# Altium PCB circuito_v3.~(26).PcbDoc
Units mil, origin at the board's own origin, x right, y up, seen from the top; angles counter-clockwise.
Board outline 6000 x 4000 mil, 2 copper layers (Top Layer, Bottom Layer); 47 components, 32 nets, 112 pads, 55 vias.
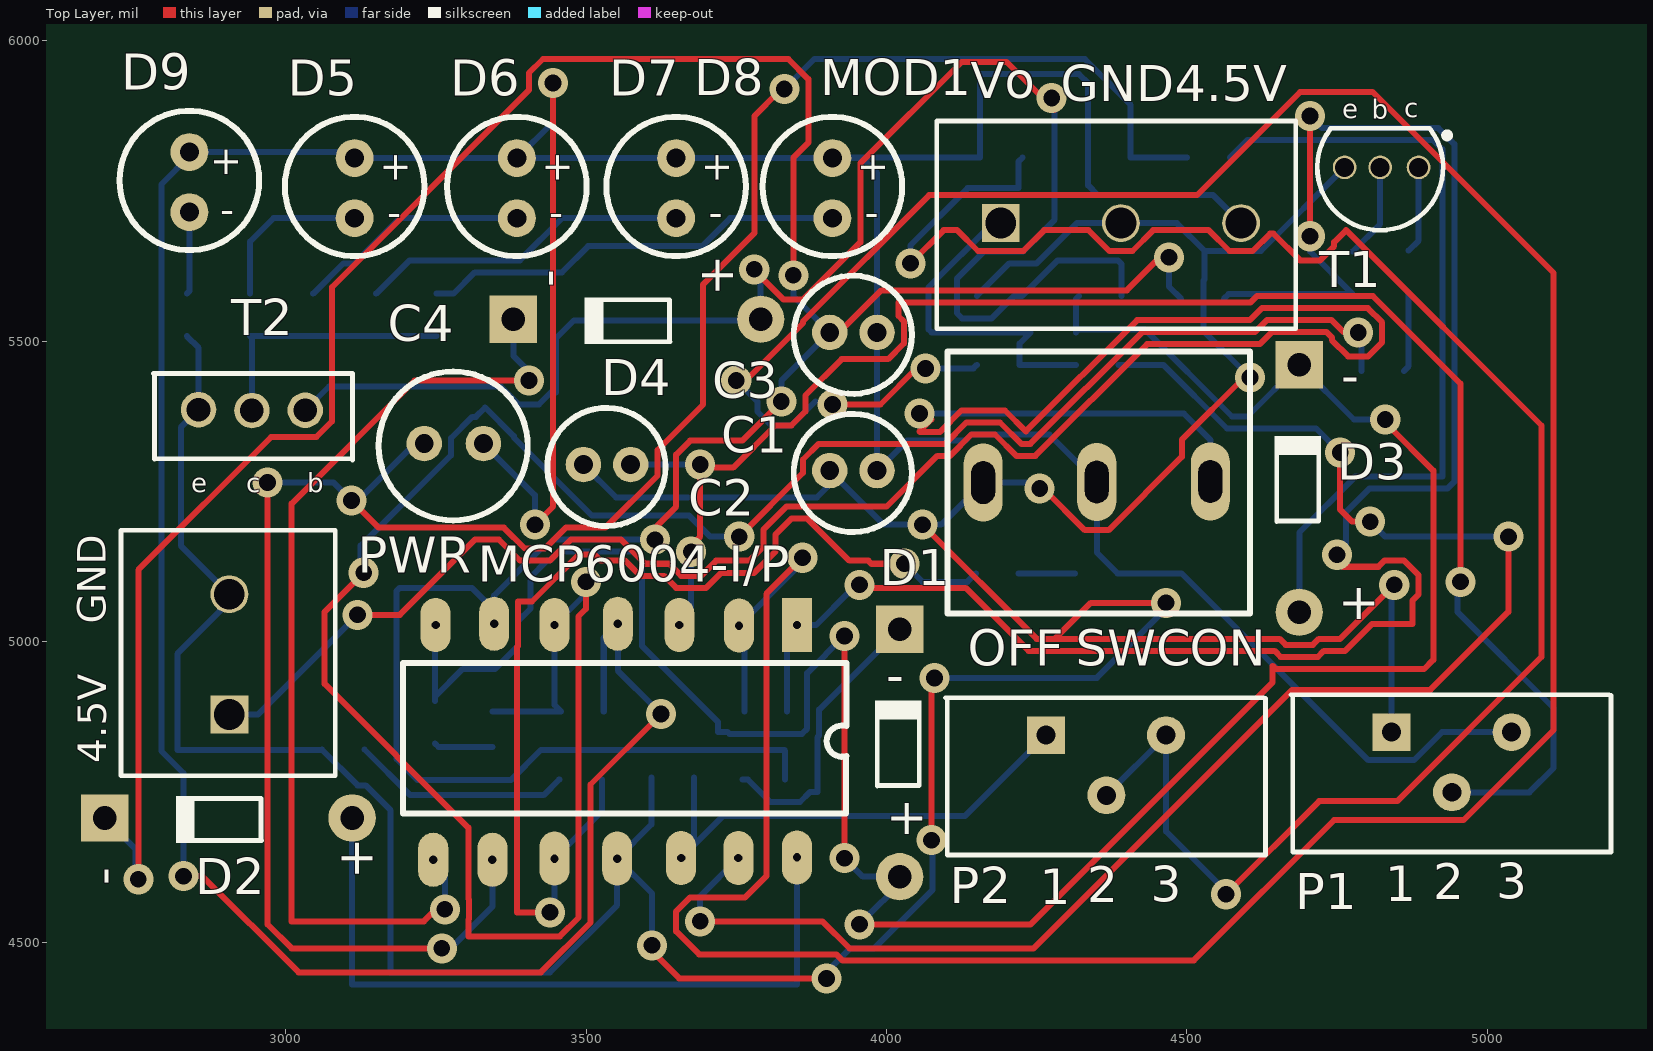
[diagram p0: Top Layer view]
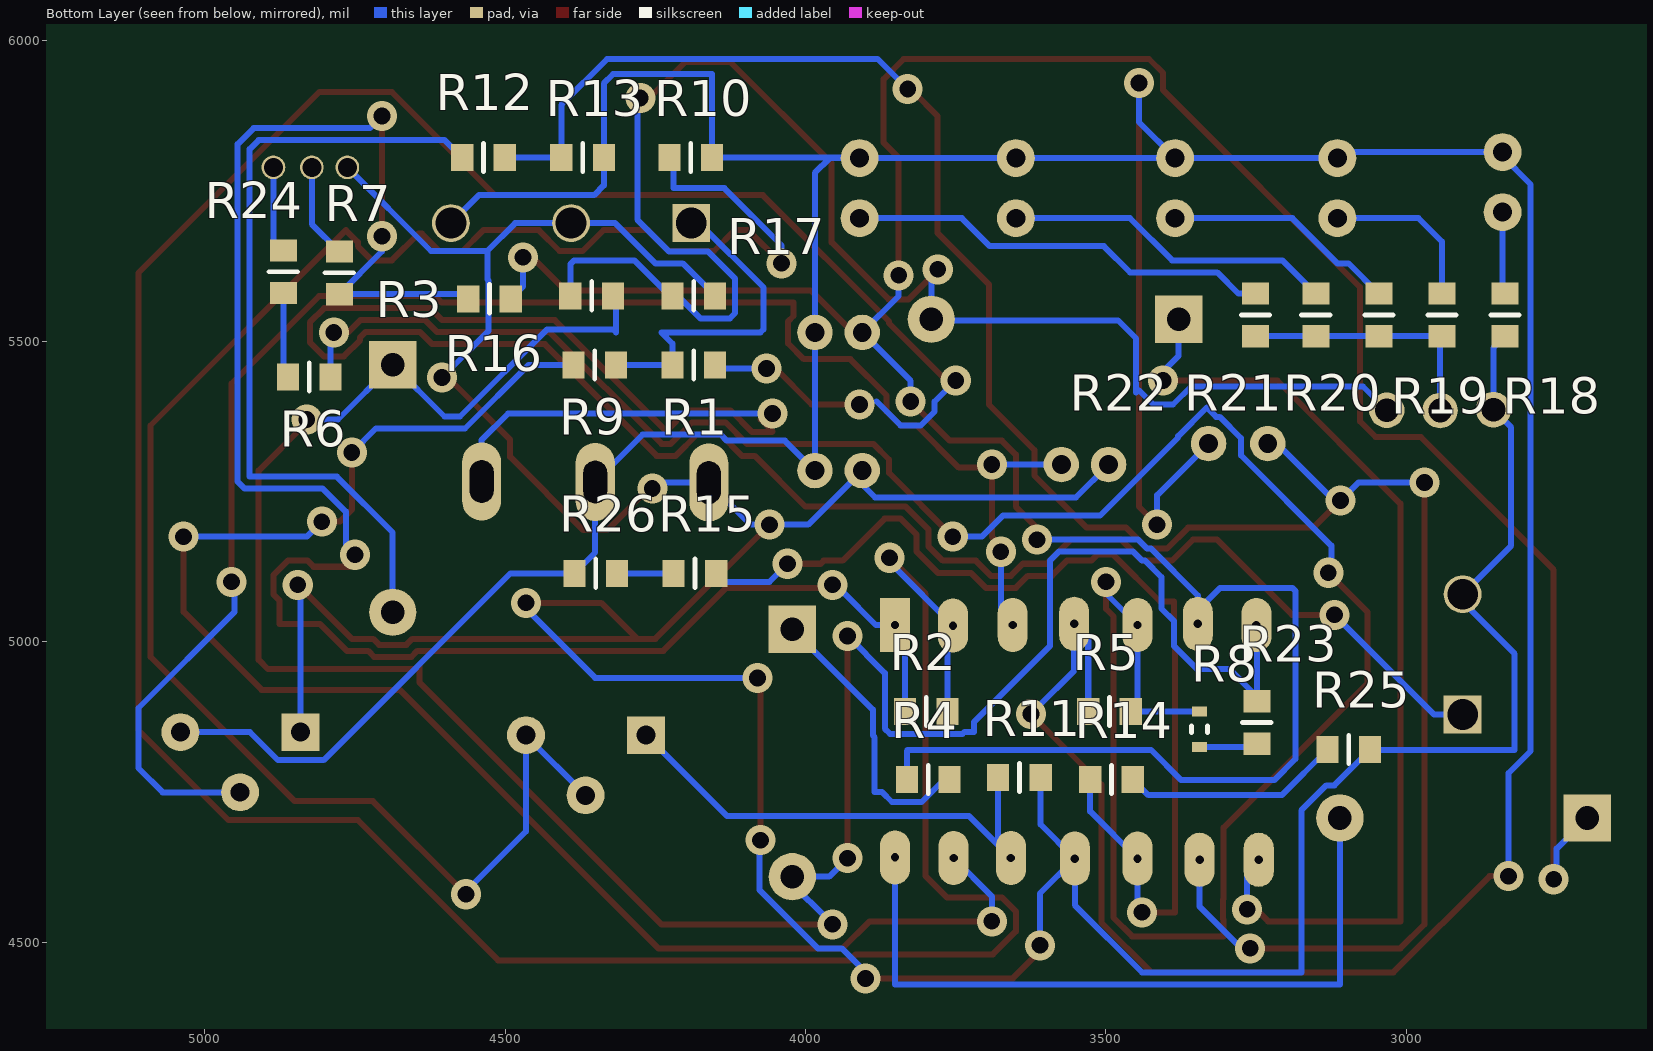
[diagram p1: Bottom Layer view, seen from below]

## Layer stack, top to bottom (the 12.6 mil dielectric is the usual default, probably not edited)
Top Layer: signal copper 1.4
Dielectric: dielectric 12.6, FR-4, Dk 4.8
Bottom Layer: signal copper 1.4

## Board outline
2580,2130 2580,6130 8580,6130 8580,2130

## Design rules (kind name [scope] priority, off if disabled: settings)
Clearance [All] p1: gap=10
FabricationTestPointUsage TestPointUsage [All] p1: valid=0 allowmultiple=FALSE
FabricationTestpoint Testpoint [All] p1: side=3 testpointundercomponent=TRUE minsize=40 maxsize=100 preferedsize=60 minholesize=0 maxholesize=40 preferedholesize=32 testpointgrid=1 allowsidetop=TRUE allowsidebottom=TRUE usegrid=TRUE gridtolerance=0.01
PolygonConnect [All] p1: connectstyle=Relief reliefconductorwidth=10 reliefentries=4 polygonreliefangle="90 Angle" airgapwidth=10
RoutingVias [All] p1: holewidth=28 width=50 viastyle="Through Hole" minholewidth=28 minwidth=50 maxholewidth=28 maxwidth=50
SilkToSolderMaskClearance SilkscreenOverComponentPads [IsPad] p1: minsilkscreentomaskgap=10 clearancetoexposedcopper=TRUE
SolderMaskExpansion [All] p1: expansion=4
Width [All] p1: maxlimit=10 minlimit=10 preferedwidth=10
25 further rules are at their usual default settings.

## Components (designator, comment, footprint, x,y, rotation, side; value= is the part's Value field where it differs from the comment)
C1 "Cap" "Condensador 5mm" 3945,5285 r0 top
C2 "Cap" "Condensador 5mm" 3535,5295 r0 top
C3 "Cap" "Condensador 5mm" 3945,5515 r0 top
C4 "Cap" "Condensador 6.3mm" 3280,5330 r0 top
D1 "BAT85" BAT85 4020,4820 r0 top
D2 "Diode BAT18" BAT85 2900,4705 r90 top
D3 "Diode BAT18" BAT85 4685,5260 r0 top
D4 "Diode BAT18" BAT85 3580,5535 r90 top
D5 "LED" LED 3115,5805 r270 top
D6 "LED" LED 3385,5805 r270 top
D7 "LED" LED 3650,5805 r270 top
D8 "LED" LED 3910,5805 r270 top
D9 "LED" "LED verde" 2840,5815 r270 top
MCP6004-I/P "MCP6004-I/P" MCP6004 3795,5035 r270 top
MOD1 "Conector" Conector 5615,5350 r270 top
P1 "Res Tap" POTENCIOMETRO 4940,4850 r270 top
P2 "Res Tap" POTENCIOMETRO 4365,4845 r270 top
PWR "Header 2" ALM 3560,5410 r90 top
R1 "Res1" "SMD 0805" 4460,5545 r180 bottom
R2 "Res1" "SMD 0805" 3525,4800 r0 bottom
R3 "Res1" "SMD 0805" 4800,5655 r180 bottom
R4 "Res1" "SMD 0805" 4070,4855 r180 bottom
R5 "Res1" "SMD 0805" 3220,4800 r0 bottom
R6 "Res1" "SMD 0805" 5100,5525 r180 bottom
R7 "Res1" "SMD 0805" 4860,5340 r90 bottom
R8 "Res1" "SMD 0603" 3345,4855 r180 bottom
R9 "Res1" "SMD 0805" 4625,5545 r180 bottom
R10 "Res1" "SMD 0805" 4465,5890 r180 bottom
R11 "Res1" "SMD 0805" 3370,4690 r0 bottom
R12 "Res1" "SMD 0805" 4810,5890 r180 bottom
R13 "Res1" "SMD 0805" 4645,5890 r180 bottom
R14 "Res1" "SMD 0805" 3765,4855 r180 bottom
R15 "Res1" "SMD 0805" 3910,5030 r0 bottom
R16 "Res1" "SMD 0805" 4630,5660 r180 bottom
R17 "Res1" "SMD 0805" 4460,5660 r180 bottom
R18 "Res3" "SMD 0805" 2920,5270 r90 bottom
R19 "Res3" "SMD 0805" 3025,5270 r90 bottom
R20 "Res3" "SMD 0805" 3130,5270 r90 bottom
R21 "Res3" "SMD 0805" 3235,5270 r90 bottom
R22 "Res3" "SMD 0805" 3335,5270 r90 bottom
R23 "Res1" "SMD 0805" 3165,5140 r270 bottom
R24 "Resistencia" "SMD 0805" 4785,5890 r270 bottom
R25 "Resistencia" "SMD 0805" 3370,4905 r180 bottom
R26 "Resistencia" "SMD 0805" 4075,5030 r0 bottom
SWC "Switch" switch 4240,5240 r0 top
T1 "2N3904" "T1 BC550C" 4415,8135 r90 top
T2 "QNPN" "T2 BD139" 2580,2850 r270 top

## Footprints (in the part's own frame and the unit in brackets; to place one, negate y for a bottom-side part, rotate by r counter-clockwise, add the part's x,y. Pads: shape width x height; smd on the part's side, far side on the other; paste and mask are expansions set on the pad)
ALM [mm]
  rect 1.6x1.6 hole 1.3: 1(-13.48,16.6)
  round 1.6 hole 1.3: 2(-8.4,16.6)
  silkscreen extent -16.07,12.12 -5.7,21.17, body extent -16.1,12.18 -4.94,21.17, height 15.2
BAT85 [mm]
  round 2 hole 1: 1(0.049,-5.353)
  rect 2x2 hole 1: 2(0.049,5.107)
  silkscreen extent -1,-1.53 0.97,2.1, body extent -1.02,-5.46 0.88,5.26, height 1.95
"Condensador 5mm" [mm]
  round 1.5 hole 0.8: 1(-1,0) 2(1,0)
  silkscreen extent -2.52,-2.6 2.47,2.4, body extent -2.45,-2.47 2.55,2.52, height 11
"Condensador 6.3mm" [mm]
  round 1.5 hole 0.8: 1(-1.25,0) 2(1.25,0)
  silkscreen extent -3.17,-3.25 3.12,3.05, body extent -3.22,-3.25 3.08,3.05, height 11.5
Conector [mm]
  rect 1.6x1.6 hole 1.3: 1(-8.811,-36.193)
  round 1.6 hole 1.3: 2(-8.811,-31.113) 3(-8.811,-26.033)
  silkscreen extent -13.13,-38.9 -4.35,-23.72, body extent -13.25,-38.87 -4.25,-23.63, height 15.2
LED [mm]
  round 1.6 hole 0.8: 1(0,0) 2(2.54,0)
  silkscreen extent -1.75,-2.95 4.15,2.95, body extent -1.68,-3.03 4.12,2.77, height 17.5
"LED verde" [mm]
  round 1.6 hole 0.8: 1(0,0) 2(2.54,0)
  silkscreen extent -1.75,-2.95 4.15,2.95, body extent -1.47,-3.12 4.23,2.87, height 20.86
MCP6004 [mil]
  rect 90x50 hole 14: 1(6.89,56.1)
  oval 90x50 hole 14: 2(7.87,-40.35) 3(6.89,-139.76) 4(4.92,-242.13) 5(6.89,-347.44) 6(4.92,-447.83) 7(6.89,-545.28) 8(397.64,-549.21) 9(397.64,-450.79) 10(395.67,-347.44) 11(395.67,-243.11) 12(394.69,-136.81) 13(394.69,-41.34) 14(393.7,56.1)
  silkscreen extent 70,-599 321,139, body extent -48,-623 452,147, height 181
POTENCIOMETRO [mm]
  rect 1.6x1.6 hole 0.8: 1(0.008,-2.535)
  round 1.6 hole 0.8: 2(2.548,0.025) 3(0.008,2.545)
  silkscreen extent -1.58,-6.78 5.07,6.75, body extent -4.59,-6.77 33.45,6.77, height 14.1
"SMD 0603" [mm]
  rect 0.64x0.44 smd mask+0.26: 1(0.018,-0.76) 2(0.018,0.74)
  silkscreen extent -0.33,-0.15 0.35,0.13, body extent -0.4,-0.9 0.4,0.8, height 0.56
"SMD 0805" [mm]
  rect 0.94x1.14 smd mask+0.26: 1(6.062,-2.136) 2(7.862,-2.136)
  silkscreen extent 6.96,-2.74 6.96,-1.54, body extent 6.08,-2.77 8.08,-1.52, height 0.78
switch [mil]
  oval 65x130 hole 39.37 slot 70.87 at 90 deg: 1(-79,25) 2(109.96,26) 3(298.94,27)
  silkscreen extent -139,-193 365,243, body extent -69,-61 250,136, height 720
"T1 BC550C" [mm]
  round 1 hole 0.8: 1(-59.575,-11.95) 2(-59.571,-10.328) 3(-59.575,-8.825)
  silkscreen extent -62.23,-13.28 -57.92,-7.67, body extent -61.73,-12.63 -58.1,-7.87, height 4.92
"T2 BD139" [mm]
  round 1.5 hole 1: 1(-64.425,6.992) 2(-64.389,9.246) 3(-64.4,11.5)
  silkscreen extent -65.95,5.07 -62.3,13.5, body extent -65.4,5.4 -62.7,13.2, height 13.6

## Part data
C1 C2 C3 C4: "Capacitor"
D1: library part "Diode BAT18", "Low-Loss RF Switching Diode"
D2 D3 D4: "Low-Loss RF Switching Diode"
D5 D6 D7 D8 D9: library part LED2, "Typical RED, GREEN, YELLOW, AMBER GaAs LED"
MCP6004-I/P: "DIP Switch, 7 Position, SPST"
MOD1: library part "Header 3", "Header, 3-Pin"
P1 P2: "Tapped Resistor"
PWR: "Header, 2-Pin"
R1 R2 R3 R4 R5 R6 R7 R8 R9 R10 R11 R12 R13 R14 R15 R16 R17 R18 R19 R20 R21 R22 R23 R24 R25 R26: "Resistor"
SWC: library part Conmutador
T1: "NPN General Purpose Amplifier"
T2: "NPN Bipolar Transistor"

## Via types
v1: diameter 50, hole 28, Top Layer to Bottom Layer, 55 vias

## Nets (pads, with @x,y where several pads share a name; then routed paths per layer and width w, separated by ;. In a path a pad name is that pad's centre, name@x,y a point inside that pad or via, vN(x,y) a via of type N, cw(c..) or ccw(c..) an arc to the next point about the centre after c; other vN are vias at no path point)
"4.5 V": C1.2 C3.2 C4.2 D5.1 D6.1 D7.1 D8.1 D9.1 MCP6004-I/P.4 MOD1.3 P1.3 R5.2 R10.2 R13.2 R26.2 SWC.2 | length 7876.9
  Top Layer w10: v1@2825,4610 v1(2830,4610) 2861.72,4610 3021.72,4450 3424.85,4450 3507.56,4532.71 3507.56,4762.56 v1(3625,4880) ; v1(3415,5195) 3445,5225 v1(3445,5930)
  Bottom Layer w10: v1(2830,4610) 2830,4781.72 2793.5,4818.21 2793.5,5761.5 2840,5807.99 D9.1 3105,5815 D5.1 D6.1 ; C4.2 3415,5244.21 v1(3415,5195) ; v1(3445,5930) 3445,5865 D6.1 ; R5.2 3529.53,5006.73 MCP6004-I/P.4 3552.87,4952.13 v1@3615,4890 ; MOD1.3 4543.58,5743.39 4351.61,5743.39 4335.47,5759.53 R13.2 4335.47,5929.53 4320,5945 4155.47,5945 R10.2 3910.91,5805.91 D8.1 ; P1.3 4924.4,4849.69 4877.91,4803.19 4801.81,4803.19 4490.91,5114.09 R26.2 4349.96,5148.66 SWC.2 4270.96,5345 4141.32,5345 4131.32,5335 4034.37,5335 C1.2 C3.2 3984.37,5780.63 3960,5805 D8.1 ; D6.1 D7.1 D8.1
GND: C1.1 C2.1 MCP6004-I/P.11 MOD1.2 P1.1 PWR.2 R11.1 R17.2 R18.1 R25.2 SWC.1 T1.3 T2.1 | length 7318.7
  Top Layer w10: v1@3615,4480 3655,4440 v1(3900,4440) ; v1(4060,5195) 4250,5005 4280,5005 ; v1@4070,4655 4075,4660 v1(4075,4670) v1@4075,4935 ; v1(4255,5255) 4261.29,5255 4330.29,5186 4369.64,5186 4491.44,5307.8 4491.44,5336.44 v1@4595,5440 ; v1(4465,5065) 4340,5065 4280,5005 ; v1(4845,5095) 4755,5005 4719.57,5005 4709.45,4994.88 4664.41,4994.88 4654.29,5005 4280,5005
  Bottom Layer w10: R18.1 2855.28,5489.29 T2.1 2825.75,5356.89 2825.75,5160 PWR.2 2906.46,5066.46 2820,4980 2820,4820 3059.57,4820 R25.2 3120.08,4761.3 3133.27,4761.3 3175,4719.57 3175,4450 3440,4450 3551.89,4561.89 MCP6004-I/P.11 ; C2.1 3550,5240.63 3884.37,5240.63 3905.63,5261.89 C1.1 3995.63,5195 v1(4060,5195) 4091,5195 SWC.1 4240,5265 v1@4245,5260 ; R11.1 3608.66,4696.1 MCP6004-I/P.11 ; v1(3610,4495) 3610,4581.22 MCP6004-I/P.11 ; v1@3890,4440 3940,4490 3979.57,4490 4076.3,4586.73 4076.3,4668.7 v1(4075,4670) ; v1(4080,4940) 4350,4940 4465,5055 v1(4465,5065) ; R17.2 4204.57,5630 4250,5630 4316.89,5696.89 MOD1.2 4483.11,5696.89 4529.61,5650.39 ; v1(4605,5440) 4527.83,5517.17 4527.83,5601.33 4529.61,5603.1 4529.61,5650.39 ; T1.3 4623.31,5650.39 4529.61,5650.39 ; P1.1 v1@4840.2,5074.8
NetD1_3: D1.2 R4.2 | length 474.7
  Bottom Layer w10: R4.2 3769.18,4770.91 3806.62,4733.46 3856.06,4733.46 3872.59,4750 3885,4750 3885,4841.09 3888.03,4844.12 3888.03,4887.17 D1.2
NetD2_1: D2.1 MCP6004-I/P.14 | length 1228.4
  Bottom Layer w10: D2.1 3110.75,4430 3850.75,4430 3850.75,4640.94 MCP6004-I/P.14
NetD3_1: D3.1 R12.1 | length 1326.2
  Bottom Layer w10: R12.1 4600.43,5835 4910,5835 4925,5820 4925,5275 4780,5275 4686.93,5181.93 D3.1
NetD4_1: D4.1 R16.1 R17.1 T2.3 | length 2585.9
  Top Layer w10: v1(3780,5620) 3780,5618.43 3828.43,5570 3861.57,5570 3956.5,5664.93 3956.5,5796.5 4125,5965 4200,5965 v1@4280,5885
  Bottom Layer w10: T2.3 3072.32,5425 3358.43,5425 3388.43,5395 3421.57,5395 3445,5418.43 3446.57,5418.43 3450,5415 3450,5505 3480,5535 3788.82,5535 D4.1 3790.75,5599.25 v1@3780,5610 ; 4280,5880 4280,5702.61 4227.39,5650 4162.41,5650 4116.97,5604.56 4116.97,5547.25 4125.76,5538.46 4175.19,5538.46 4212.63,5575.91 R17.1 4225.91,5575.91 4285,5635 4385,5635 4391.34,5628.66 R16.1
  other v1: 4275,5905
NetD5_2: D5.2 R19.2 | length 276.7
  Bottom Layer w10: R19.2 2940.91,5665.91 2980,5705 D5.2
NetD6_2: D6.2 R20.2 | length 391.1
  Bottom Layer w10: R20.2 3096.38,5630 3115,5630 3190,5705 D6.2
NetD7_2: D7.2 R21.2 | length 551.1
  Bottom Layer w10: R21.2 3206.38,5635 3390,5635 3460,5705 D7.2
NetD8_2: D8.2 R22.2 | length 711.1
  Bottom Layer w10: R22.2 3279.53,5579.53 3315,5615 3460,5615 3503.5,5658.5 3693.5,5658.5 3740,5705 D8.2
NetD9_2: D9.2 R18.2 | length 137.2
  Bottom Layer w10: R18.2 2840,5583.62 D9.2
NetMOD1_1: MOD1.1 R1.1 R9.2 | length 562.4
  Bottom Layer w10: MOD1.1 4176.89,5696.89 4070,5590 4070,5520 4075,5515 4240,5515 4221.34,5496.34 R1.1 R9.2
NetP2_1: P2.2 P2.3 R10.1 | length 3137.7
  Top Layer w10: v1(4040,5630) 4095,5685 4117.76,5685 4152.37,5650.39 4227.79,5650.39 4262.39,5685 4336.21,5685 4370.82,5650.39 4409.34,5650.39 4443.94,5685 4536.21,5685 4570.82,5650.39 4609.34,5650.39 4638.37,5679.43 4644,5679.43 4688.43,5635 4721.57,5635 4745,5658.43 4745,5665 4765,5685 5090,5360 5090,4975 4850,4735 4720,4735 v1(4565,4580)
  Bottom Layer w10: v1(4040,5630) 4040,5660 4135,5755 4220,5755 4220,5799.57 R10.1 ; P2.2 P2.3@4465.2,4843.9 ; P2.3 P2.3@4465.2,4843.9 ; v1@4555,4595 4465.2,4684.8 P2.3@4465.2,4843.9
NetPWR_1: PWR.1 SWC.3 | length 3862.6
  Top Layer w10: v1(3120,5045) 3190.05,5045 3315.05,5170 3355.15,5170 3390.15,5135 3439.85,5135 3474.85,5170 3558.43,5170 3598.43,5130 3638.43,5130 3658.43,5110 3691.57,5110 3716.57,5135 3771.57,5135 3795,5158.43 3795,5186.72 3833.28,5225 4000,5225 4084.53,5309.53 4105.85,5309.53 4141.32,5345 4180.68,5345 4216.15,5309.53 4247.81,5309.53 4433.72,5495.43 4621.35,5495.43 4641.35,5515.43 4732.51,5515.43 4741.3,5506.65 4741.3,5502.13 4768.43,5475 4801.57,5475 4825,5498.43 4825,5531.57 4801.14,5555.43 4624.78,5555.43 4604.78,5535.43 4417.15,5535.43 4231.98,5350.26 4197.24,5385 4124.76,5385 4089.28,5349.53 4055.47,5349.53 4055,5350 v1@4075,5370
  Bottom Layer w10: PWR.1 2954.29,4879.29 v1(3120,5045) ; v1(4055,5380) 4495,5380 4538.94,5336.06 SWC.3
NetR6_1: R6.1 R24.2 | length 132.8
  Bottom Layer w10: R6.1@4861.34,5450.91 4869.09,5458.66 R24.2
NetR7_2: R7.2 T1.2 | length 159.1
  Bottom Layer w10: R7.2 4821.61,5695.24 T1.2
NetR8_1: R8.1 R23.2 | length 97.4
  Bottom Layer w10: R23.2 3254.49,4825.08 R8.1
NetR14_2: R14.2 R25.1 | length 366.3
  Bottom Layer w10: R25.1 3207.24,4745 3429.57,4745 R14.2
NetR15_2: R15.2 R26.1 | length 94.1
  Bottom Layer w10: R15.2 R26.1
NetR19_1: R19.1 R20.1 R21.1 R22.1 T2.2 | length 434.9
  Bottom Layer w10: T2.2 2944.02,5505.55 R19.1 R20.1 R21.1 R22.1
NetR24_1: R24.1 T1.1 | length 145
  Bottom Layer w10: R24.1 4885.47,5667.72 T1.1
VA+: C2.2 MCP6004-I/P.3 P1.2 | length 2760.6
  Top Layer w10: v1@3680,5165 3690,5175 v1(3690,5295) 3695,5290 3745,5290 3815,5360 3841.57,5360 3865,5383.43 3865,5410 3925.47,5470.47 4002.81,5470.47 4028.9,5496.56 4028.9,5533.44 4020,5542.34 4020,5565 4606.06,5565 4616.49,5575.43 4809.57,5575.43 4955,5430 v1(4955,5100)
  Bottom Layer w10: C2.2 v1@3675,5295 ; MCP6004-I/P.3 3675,5047.87 v1(3675,5150) ; P1.2 5069.69,4749.69 5110,4790 5110,4890 4950,5050 v1@4950,5090
VA-: MCP6004-I/P.2 R1.2 R2.1 | length 5580.1
  Top Layer w10: v1(3750,5435) 3765.71,5435 3861.1,5530.39 3861.1,5533.44 4071.04,5743.39 4516.82,5743.39 4688.43,5915 4809.05,5915 5110,5614.05 5110,4852.95 4960.24,4703.19 4744.76,4703.19 4511.57,4470 3926.57,4470 3916.57,4480 3688.43,4480 3650,4518.43 3650,4551.57 3673.43,4575 3764.91,4575 3800,4610.09 3800,5080 v1(3860,5140) ; v1(3910,5395) 3990,5395 v1@4050,5455
  Bottom Layer w10: v1(3750,5435) 3785,5400 3785,5383.43 3808.43,5360 3841.57,5360 3881.57,5400 ; R2.1 3763.66,5018.11 MCP6004-I/P.2 3855,5127.48 v1@3855,5130 ; v1(4065,5455) 4144.57,5455 R1.2
VB+: MCP6004-I/P.5 R5.1 R6.2 R8.2 | length 3997.6
  Top Layer w10: v1(3130,5115) 3065,5050 3065,4930 3304.21,4690.79 3304.21,4572.36 3305,4571.57 3305,4538.43 3304.21,4537.64 3304.21,4510 3456.57,4510 3487.56,4540.99 3487.56,5042.56 3500,5055 v1(3500,5100) ; v1(3755,5175) 3861.1,5281.1 3861.1,5303.44 3887.19,5329.53 4097.57,5329.53 4133.04,5365 4188.96,5365 4224.43,5329.53 4239.53,5329.53 4425.43,5515.43 4613.06,5515.43 4633.06,5535.43 4740.8,5535.43 4760.8,5515.43 4784.57,5515.43 v1(4785,5515)
  Bottom Layer w10: 3125,5140 3125,5160 3275.32,5310.31 3275.32,5339.07 3310.77,5374.53 3316.71,5374.53 3332.18,5390 3380,5342.18 3380,5340 3510,5210 3671.57,5210 3706.57,5175 v1(3755,5175) ; R8.2 3458.62,4884.13 3447.56,4895.2 MCP6004-I/P.5 3500,5080.55 v1(3500,5100) ; v1(4785,5515) 4790.47,5509.53 R6.2@4790.47,5450.91
VB-: C3.1 D2.2 MCP6004-I/P.6 R3.2 R4.1 | length 5496.1
  Top Layer w10: v1(2755,4605) 2755,5120 2975.91,5340.91 3051.2,5340.91 3077.28,5366.99 3077.28,5590.28 3405,5917.99 3405,5946.57 3428.43,5970 3836.57,5970 3870,5936.57 3870,5830.76 3845,5805.76 v1(3845,5610) ; v1(3615,5170) 3615,5190 3650,5225 3650,5311.57 3673.43,5335 3760,5335 v1(3825,5400) ; C3.1 3921.4,5515 3991.4,5585 4400,5585 v1@4460,5645
  Bottom Layer w10: D2.2 2750,4655.87 v1@2750,4600 ; v1(3615,5170) 3446.57,5170 3431.57,5155 3425,5155 3347.17,5077.17 MCP6004-I/P.6 3347.17,5052.83 3310,5090 3190,5090 3185,5085 3185,4805 3220,4770 3375,4770 3425,4820 3830,4820 3831.34,4818.66 R4.1 ; v1(3825,5400) 3825,5434.37 C3.1 3845,5575.63 v1(3845,5610) ; v1(4470,5640) 4470,5591.38 R3.2
VC+: MCP6004-I/P.10 R14.1 R15.1 | length 1759.8
  Top Layer w10: v1(3440,4550) 3385,4550 3385,4991.34 3387.17,4993.51 3387.17,5067.17 3410.05,5067.17 3487.88,5145 3514.52,5145 3524.52,5135 3565.15,5135 3590.15,5110 3630.15,5110 3650.15,5090 3699.85,5090 3724.85,5115 3779.85,5115 3815,5150.15 3815,5178.43 3841.57,5205 3868.28,5205 3938.28,5135 3970,5135 3975,5130 v1(4030,5130)
  Bottom Layer w10: v1(3440,4550) 3447.56,4557.56 MCP6004-I/P.10 3526.34,4718.11 R14.1 ; v1(4030,5130) 4060,5100 4134.57,5100 R15.1
VC-: C4.1 MCP6004-I/P.9 R12.2 R13.1 | length 3635.7
  Top Layer w10: v1(2970,5265) 2970,4530 3010,4490 v1(3260,4490) ; v1(3110,5235) 3155,5190 3363.43,5190 3398.43,5155 3431.57,5155 3466.57,5190 3532.34,5190 3618.9,5276.56 3618.9,5318.9 3695,5395 3695,5595 3780,5680 3780,5875 v1@3820,5915
  Bottom Layer w10: v1(2970,5265) 3080,5265 v1(3110,5235) ; v1@3120,5240 3125,5240 3215,5330 C4.1 ; v1@3280,4495 3344.21,4559.21 MCP6004-I/P.9 ; v1(3830,5920) 3880,5970 4330,5970 4406.34,5893.66 R13.1 R12.2
VD+: MCP6004-I/P.12 P2.1 R11.2 | length 804.1
  Bottom Layer w10: MCP6004-I/P.12 MCP6004-I/P.12@3679.53,4661.65 ; R11.2 MCP6004-I/P.12@3679.53,4661.65 ; P2.1 4130.51,4710 3727.87,4710 MCP6004-I/P.12@3679.53,4661.65
VD-: MCP6004-I/P.13 R9.1 | length 2675
  Top Layer w10: v1(3690,4535) 3893.43,4535 3938.43,4490 4245,4490 4675,4920 4905,4920 5035,5050 v1(5035,5175) ; v1(4755,5315) 4755,5220 4775,5200 v1(4805,5200)
  Bottom Layer w10: v1(3690,4535) 3690,4576.65 MCP6004-I/P.13 ; R9.1 4460.81,5460.91 4566.72,5355 4715,5355 v1(4755,5315) ; v1(4805,5200) 4830,5175 v1(5035,5175)
VOUTA: MCP6004-I/P.1 R2.2 R3.1 R7.1 | length 3130.5
  Top Layer w10: v1(3955,5095) 3960,5090 4131.72,5090 4236.72,4985 4646.01,4985 4656.12,4974.88 4717.73,4974.88 4727.85,4985 4763.28,4985 4808.28,5030 4875,5030 4875,5068.43 4885,5078.43 4885,5111.57 4861.57,5135 4828.43,5135 4818.43,5125 4760,5125 v1@4765,5130 ; v1(4705,5675) v1(4705,5875)
  Bottom Layer w10: R2.2 3834.53,5011.54 MCP6004-I/P.1 3883.11,5028.11 v1@3940,5085 ; R3.1 4569.09,5578.66 R7.1 4705,5649.57 v1(4705,5675) ; v1(4705,5875) 4725,5855 4918.28,5855 4945,5828.28 4945,5266.72 4933.28,5255 4803.43,5255 4765,5216.57 4765,5160 v1(4750,5145)
VOUTB: D1.1 D3.2 MCP6004-I/P.7 R16.2 R23.1 | length 4169.7
  Top Layer w10: v1(3930,4640) v1(3930,5010) v1@3935,5015 ; v1(3955,4530) 4240,4530 4642.72,4932.72 4642.72,4960 4647.84,4954.88 4894.88,4954.88 4910,4970 4910,5285 v1@4835,5360
  Bottom Layer w10: R23.1 R23.1@3249.09,4909.09 ; MCP6004-I/P.7 3249.09,5027.48 R23.1@3249.09,4909.09 ; v1(3930,4640) 3960.75,4609.25 D1.1 4021.93,4596.93 v1@3965,4540 ; v1(3930,5010) 3868.03,4948.03 3868.03,4855.44 3859.24,4846.65 3738.94,4846.65 3735.6,4850 3720,4850 3720,4866.38 3592.87,4993.51 3592.87,5135.56 3578.43,5150 3454.85,5150 3439.85,5135 3435,5135 3407.56,5107.56 3407.56,5055.39 3387.17,5035 3387.17,4993.51 3348.66,4955 3295,4955 R23.1@3249.09,4909.09 ; R16.2 4315,5570.43 4315,5515 4320,5520 4430,5520 4575,5375 4600.87,5375 D3.2 4777.99,5370 v1(4830,5370)
VOUTC: D4.2 MCP6004-I/P.8 | length 1597.1
  Top Layer w10: v1@3245,4550 3230,4535 3010,4535 3010,5230 3215,5435 v1(3405,5435)
  Bottom Layer w10: MCP6004-I/P.8 3265,4618.15 v1(3265,4555) ; D4.2 3378.94,5476.06 v1@3400,5455

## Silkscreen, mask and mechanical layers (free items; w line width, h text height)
Mechanical 16:
  drawing of 1874 lines, arcs and shapes, not listed
  text "1" at 1427,7465 h70
  text "2" at 4287,7465 h70
  text "3" at 7167,7465 h70
  text "4" at 10037,7465 h70
  text "A" at 75,6559 h70
  text "A" at 11375,6559 h70
  text "B" at 75,4667 h70
  text "B" at 11375,4667 h70
  text "C" at 4158.07,3082.75 h70
  text "C" at 75,2757 h70
  text "ENGINEER:" at 6850,1300 h45
  text "TITLE:" at 8350,1300 h45
  text "PCB DESIGNER:" at 6850,1005 h45
  text "D" at 75,867 h70
  text "D" at 11375,867 h70
  text "DATE:" at 6850,700 h45
  text "PART NO.:" at 8350,700 h45
  text "REV:" at 10450,700 h45
  text "Altium Limited" at 5550,600 h70
  text ".PRINT_DATE" at 6900,580 h70
  text "12a Rodborough Rd" at 5550,500 h70
  text "Frenchs Forest" at 5550,400 h70
  text "FILE NAME:" at 6850,400 h45
  text "DWG NO:" at 8350,400 h45
  text "SCALE:" at 10450,400 h45
  text "NSW 2086" at 5550,300 h70
  text ".PCB_FILE_NAME_NO_PATH" at 6900,280 h70
  text "1" at 1427,65 h70
  text "2" at 4287,65 h70
  text "3" at 7167,65 h70
  text "4" at 10037,65 h70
